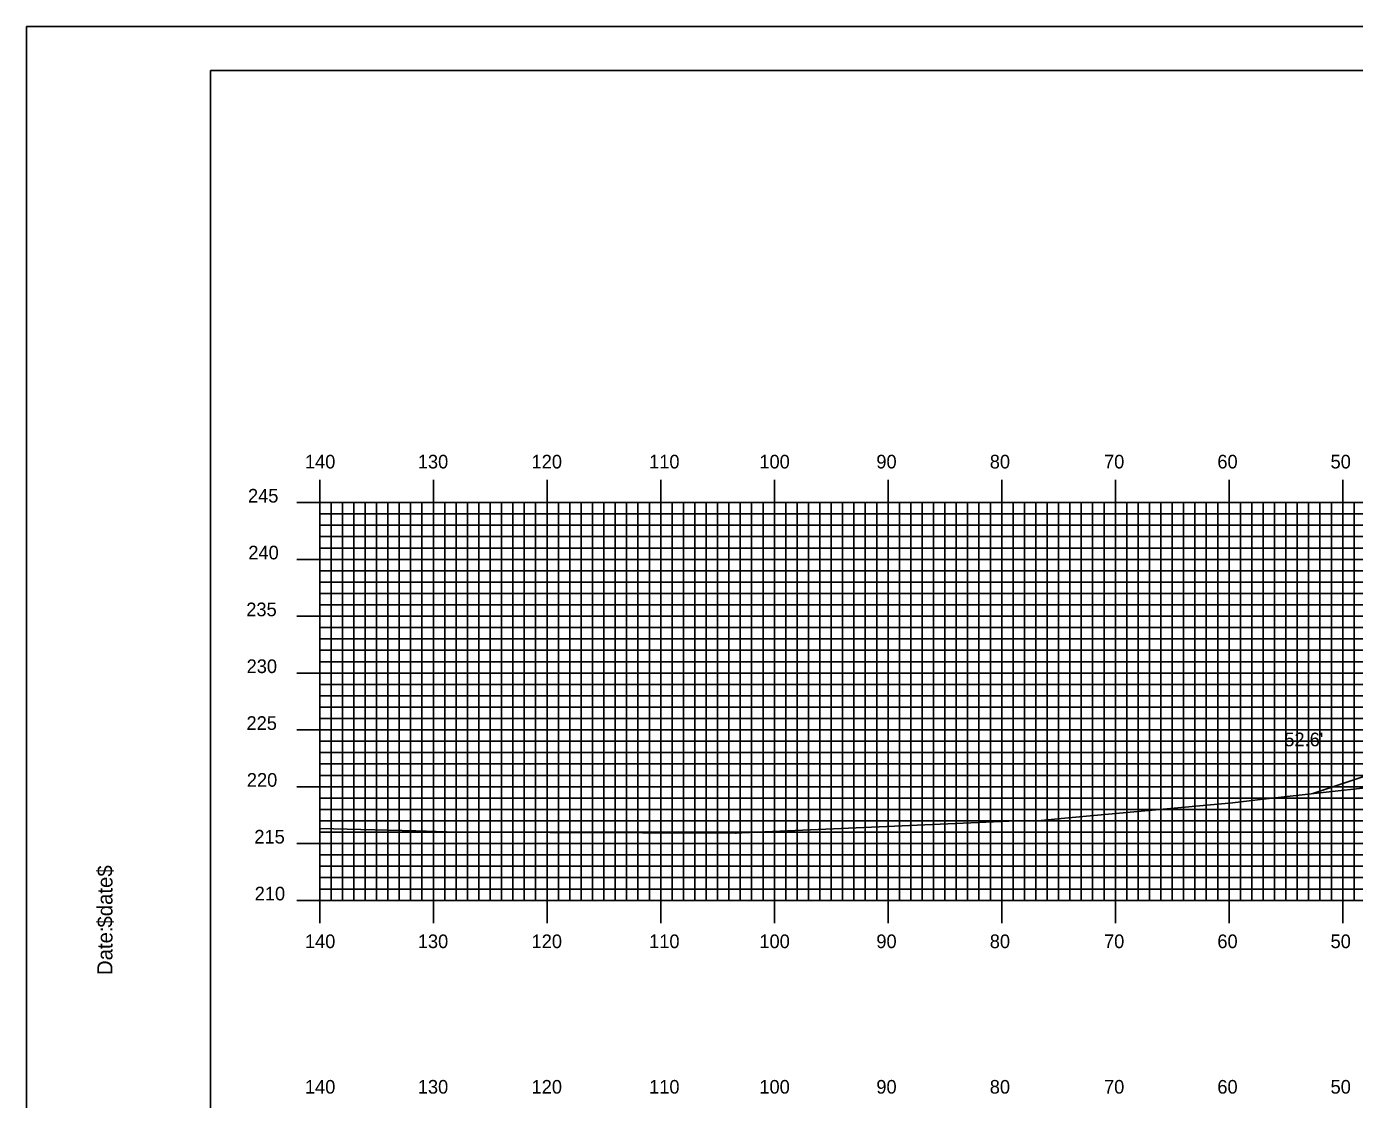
# Model space of a CAD drawing. Extents: x 1818457 to 1818800, y 442591 to 442811.
# Drawn here: x 1818456.9 to 1818573.7, y 442716.2 to 442810.5 of the extents above; entities that cross this region are included whole.
import ezdxf

# ---------------------------------------------------------------- set-up
doc = ezdxf.new("R2010")
doc.units = 0
for name, color, linetype in [('BORDER', 7, 'Continuous'), ('D_Roadway_Centerline', 7, 'Continuous'), ('D_Roadway_SlopeLines', 7, 'Continuous'), ('D_Text_Standard', 7, 'Continuous'), ('H_V ANNOTATION', 7, 'Continuous'), ('MAJOR', 7, 'Continuous'), ('MINOR', 7, 'Continuous'), ('PLOT BOUNDARY', 7, 'Continuous'), ('S_Roadway_Centerline', 7, 'Continuous')]:
    doc.layers.add(name, color=color, linetype=linetype)

msp = doc.modelspace()

# ---------------------------------------------------------------- linework, layer by layer
at = {"layer": 'BORDER'}
msp.add_lwpolyline([(1818473.04, 442596.67), (1818793.04, 442596.67), (1818793.04, 442806.67), (1818473.04, 442806.67)], close=True, dxfattribs=at)
at = {"layer": 'D_Roadway_Centerline'}
msp.add_lwpolyline([(1818570, 442743.06), (1818590.64, 442749.94), (1818592.46, 442750.4), (1818602.64, 442752.94), (1818610.64, 442753.26), (1818622.64, 442753.5), (1818634.64, 442753.26), (1818642.64, 442752.94), (1818652.81, 442750.4), (1818656.81, 442749.4), (1818667.98, 442753.12), (1818669.23, 442753.51), (1818670.48, 442753.82), (1818671.73, 442754.08), (1818672.98, 442754.27)], dxfattribs=at)
at = {"layer": 'D_Roadway_SlopeLines'}
msp.add_lwpolyline([(1818602.64, 442752.94), (1818590.64, 442749.94), (1818570, 442743.06)], dxfattribs=at)
at = {"layer": 'MAJOR'}
for p, q in [((1818482.64, 442770.67), (1818482.64, 442768.67)), ((1818492.64, 442770.67), (1818492.64, 442768.67)), ((1818502.64, 442770.67), (1818502.64, 442768.67)), ((1818512.64, 442770.67), (1818512.64, 442768.67)), ((1818522.64, 442770.67), (1818522.64, 442768.67)), ((1818532.64, 442770.67), (1818532.64, 442768.67)), ((1818542.64, 442770.67), (1818542.64, 442768.67)), ((1818552.64, 442770.67), (1818552.64, 442768.67)), ((1818562.64, 442770.67), (1818562.64, 442768.67)), ((1818572.64, 442770.67), (1818572.64, 442768.67)), ((1818480.63, 442768.67), (1818482.64, 442768.67)), ((1818482.64, 442768.67), (1818762.64, 442768.67)), ((1818482.64, 442733.67), (1818482.64, 442768.67)), ((1818482.64, 442733.67), (1818482.64, 442768.67)), ((1818482.64, 442768.67), (1818762.64, 442768.67)), ((1818492.64, 442733.67), (1818492.64, 442768.67)), ((1818502.64, 442733.67), (1818502.64, 442768.67)), ((1818512.64, 442733.67), (1818512.64, 442768.67)), ((1818522.64, 442733.67), (1818522.64, 442768.67)), ((1818532.64, 442733.67), (1818532.64, 442768.67)), ((1818542.64, 442733.67), (1818542.64, 442768.67)), ((1818552.64, 442733.67), (1818552.64, 442768.67)), ((1818562.64, 442733.67), (1818562.64, 442768.67)), ((1818572.64, 442733.67), (1818572.64, 442768.67)), ((1818480.63, 442763.67), (1818482.64, 442763.67)), ((1818482.64, 442763.67), (1818762.64, 442763.67)), ((1818480.63, 442758.67), (1818482.64, 442758.67)), ((1818482.64, 442758.67), (1818762.64, 442758.67)), ((1818480.63, 442753.67), (1818482.64, 442753.67)), ((1818482.64, 442753.67), (1818762.64, 442753.67)), ((1818480.63, 442748.67), (1818482.64, 442748.67)), ((1818482.64, 442748.67), (1818762.64, 442748.67)), ((1818480.63, 442743.67), (1818482.64, 442743.67)), ((1818482.64, 442743.67), (1818762.64, 442743.67)), ((1818480.63, 442738.67), (1818482.64, 442738.67)), ((1818482.64, 442738.67), (1818762.64, 442738.67)), ((1818480.63, 442733.67), (1818482.64, 442733.67)), ((1818482.64, 442733.67), (1818762.64, 442733.67)), ((1818482.64, 442733.67), (1818762.64, 442733.67)), ((1818482.64, 442731.66), (1818482.64, 442733.67)), ((1818492.64, 442731.66), (1818492.64, 442733.67)), ((1818502.64, 442731.66), (1818502.64, 442733.67)), ((1818512.64, 442731.66), (1818512.64, 442733.67)), ((1818522.64, 442731.66), (1818522.64, 442733.67)), ((1818532.64, 442731.66), (1818532.64, 442733.67)), ((1818542.64, 442731.66), (1818542.64, 442733.67)), ((1818552.64, 442731.66), (1818552.64, 442733.67)), ((1818562.64, 442731.66), (1818562.64, 442733.67)), ((1818572.64, 442731.66), (1818572.64, 442733.67))]:
    msp.add_line(p, q, dxfattribs=at)
at = {"layer": 'MINOR'}
for p, q in [((1818483.64, 442733.67), (1818483.64, 442768.67)), ((1818484.64, 442733.67), (1818484.64, 442768.67)), ((1818485.64, 442733.67), (1818485.64, 442768.67)), ((1818486.64, 442733.67), (1818486.64, 442768.67)), ((1818487.64, 442733.67), (1818487.64, 442768.67)), ((1818488.64, 442733.67), (1818488.64, 442768.67)), ((1818489.64, 442733.67), (1818489.64, 442768.67)), ((1818490.64, 442733.67), (1818490.64, 442768.67)), ((1818491.64, 442733.67), (1818491.64, 442768.67)), ((1818493.64, 442733.67), (1818493.64, 442768.67)), ((1818494.64, 442733.67), (1818494.64, 442768.67)), ((1818495.64, 442733.67), (1818495.64, 442768.67)), ((1818496.64, 442733.67), (1818496.64, 442768.67)), ((1818497.64, 442733.67), (1818497.64, 442768.67)), ((1818498.64, 442733.67), (1818498.64, 442768.67)), ((1818499.64, 442733.67), (1818499.64, 442768.67)), ((1818500.64, 442733.67), (1818500.64, 442768.67)), ((1818501.64, 442733.67), (1818501.64, 442768.67)), ((1818503.64, 442733.67), (1818503.64, 442768.67)), ((1818504.64, 442733.67), (1818504.64, 442768.67)), ((1818505.64, 442733.67), (1818505.64, 442768.67)), ((1818506.64, 442733.67), (1818506.64, 442768.67)), ((1818507.64, 442733.67), (1818507.64, 442768.67)), ((1818508.64, 442733.67), (1818508.64, 442768.67)), ((1818509.64, 442733.67), (1818509.64, 442768.67)), ((1818510.64, 442733.67), (1818510.64, 442768.67)), ((1818511.64, 442733.67), (1818511.64, 442768.67)), ((1818513.64, 442733.67), (1818513.64, 442768.67)), ((1818514.64, 442733.67), (1818514.64, 442768.67)), ((1818515.64, 442733.67), (1818515.64, 442768.67)), ((1818516.64, 442733.67), (1818516.64, 442768.67)), ((1818517.64, 442733.67), (1818517.64, 442768.67)), ((1818518.64, 442733.67), (1818518.64, 442768.67)), ((1818519.64, 442733.67), (1818519.64, 442768.67)), ((1818520.64, 442733.67), (1818520.64, 442768.67)), ((1818521.64, 442733.67), (1818521.64, 442768.67)), ((1818523.64, 442733.67), (1818523.64, 442768.67)), ((1818524.64, 442733.67), (1818524.64, 442768.67)), ((1818525.64, 442733.67), (1818525.64, 442768.67)), ((1818526.64, 442733.67), (1818526.64, 442768.67)), ((1818527.64, 442733.67), (1818527.64, 442768.67)), ((1818528.64, 442733.67), (1818528.64, 442768.67)), ((1818529.64, 442733.67), (1818529.64, 442768.67)), ((1818530.64, 442733.67), (1818530.64, 442768.67)), ((1818531.64, 442733.67), (1818531.64, 442768.67)), ((1818533.64, 442733.67), (1818533.64, 442768.67)), ((1818534.64, 442733.67), (1818534.64, 442768.67)), ((1818535.64, 442733.67), (1818535.64, 442768.67)), ((1818536.64, 442733.67), (1818536.64, 442768.67)), ((1818537.64, 442733.67), (1818537.64, 442768.67)), ((1818538.64, 442733.67), (1818538.64, 442768.67)), ((1818539.64, 442733.67), (1818539.64, 442768.67)), ((1818540.64, 442733.67), (1818540.64, 442768.67)), ((1818541.64, 442733.67), (1818541.64, 442768.67)), ((1818543.64, 442733.67), (1818543.64, 442768.67)), ((1818544.64, 442733.67), (1818544.64, 442768.67)), ((1818545.64, 442733.67), (1818545.64, 442768.67)), ((1818546.64, 442733.67), (1818546.64, 442768.67)), ((1818547.64, 442733.67), (1818547.64, 442768.67)), ((1818548.64, 442733.67), (1818548.64, 442768.67)), ((1818549.64, 442733.67), (1818549.64, 442768.67)), ((1818550.64, 442733.67), (1818550.64, 442768.67)), ((1818551.64, 442733.67), (1818551.64, 442768.67)), ((1818553.64, 442733.67), (1818553.64, 442768.67)), ((1818554.64, 442733.67), (1818554.64, 442768.67)), ((1818555.64, 442733.67), (1818555.64, 442768.67)), ((1818556.64, 442733.67), (1818556.64, 442768.67)), ((1818557.64, 442733.67), (1818557.64, 442768.67)), ((1818558.64, 442733.67), (1818558.64, 442768.67)), ((1818559.64, 442733.67), (1818559.64, 442768.67)), ((1818560.64, 442733.67), (1818560.64, 442768.67)), ((1818561.64, 442733.67), (1818561.64, 442768.67)), ((1818563.64, 442733.67), (1818563.64, 442768.67)), ((1818564.64, 442733.67), (1818564.64, 442768.67)), ((1818565.64, 442733.67), (1818565.64, 442768.67)), ((1818566.64, 442733.67), (1818566.64, 442768.67)), ((1818567.64, 442733.67), (1818567.64, 442768.67)), ((1818568.64, 442733.67), (1818568.64, 442768.67)), ((1818569.64, 442733.67), (1818569.64, 442768.67)), ((1818570.64, 442733.67), (1818570.64, 442768.67)), ((1818571.64, 442733.67), (1818571.64, 442768.67)), ((1818573.64, 442733.67), (1818573.64, 442768.67)), ((1818482.64, 442767.67), (1818762.64, 442767.67)), ((1818482.64, 442767.67), (1818484.64, 442767.67)), ((1818482.64, 442766.67), (1818762.64, 442766.67)), ((1818482.64, 442766.67), (1818484.64, 442766.67)), ((1818482.64, 442765.67), (1818762.64, 442765.67)), ((1818482.64, 442765.67), (1818484.64, 442765.67)), ((1818482.64, 442764.67), (1818762.64, 442764.67)), ((1818482.64, 442764.67), (1818484.64, 442764.67)), ((1818482.64, 442762.67), (1818762.64, 442762.67)), ((1818482.64, 442762.67), (1818484.64, 442762.67)), ((1818482.64, 442761.67), (1818762.64, 442761.67)), ((1818482.64, 442761.67), (1818484.64, 442761.67)), ((1818482.64, 442760.67), (1818762.64, 442760.67)), ((1818482.64, 442760.67), (1818484.64, 442760.67)), ((1818482.64, 442759.67), (1818762.64, 442759.67)), ((1818482.64, 442759.67), (1818484.64, 442759.67)), ((1818482.64, 442757.67), (1818762.64, 442757.67)), ((1818482.64, 442757.67), (1818484.64, 442757.67)), ((1818482.64, 442756.67), (1818762.64, 442756.67)), ((1818482.64, 442756.67), (1818484.64, 442756.67)), ((1818482.64, 442755.67), (1818762.64, 442755.67)), ((1818482.64, 442755.67), (1818484.64, 442755.67)), ((1818482.64, 442754.67), (1818762.64, 442754.67)), ((1818482.64, 442754.67), (1818484.64, 442754.67)), ((1818482.64, 442752.67), (1818762.64, 442752.67)), ((1818482.64, 442752.67), (1818484.64, 442752.67)), ((1818482.64, 442751.67), (1818762.64, 442751.67)), ((1818482.64, 442751.67), (1818484.64, 442751.67)), ((1818482.64, 442750.67), (1818762.64, 442750.67)), ((1818482.64, 442750.67), (1818484.64, 442750.67)), ((1818482.64, 442749.67), (1818762.64, 442749.67)), ((1818482.64, 442749.67), (1818484.64, 442749.67)), ((1818482.64, 442747.67), (1818762.64, 442747.67)), ((1818482.64, 442747.67), (1818484.64, 442747.67)), ((1818482.64, 442746.67), (1818762.64, 442746.67)), ((1818482.64, 442746.67), (1818484.64, 442746.67)), ((1818482.64, 442745.67), (1818762.64, 442745.67)), ((1818482.64, 442745.67), (1818484.64, 442745.67)), ((1818482.64, 442744.67), (1818762.64, 442744.67)), ((1818482.64, 442744.67), (1818484.64, 442744.67)), ((1818482.64, 442742.67), (1818762.64, 442742.67)), ((1818482.64, 442742.67), (1818484.64, 442742.67)), ((1818482.64, 442741.67), (1818762.64, 442741.67)), ((1818482.64, 442741.67), (1818484.64, 442741.67)), ((1818482.64, 442740.67), (1818762.64, 442740.67)), ((1818482.64, 442740.67), (1818484.64, 442740.67)), ((1818482.64, 442739.67), (1818762.64, 442739.67)), ((1818482.64, 442739.67), (1818484.64, 442739.67)), ((1818482.64, 442737.67), (1818762.64, 442737.67)), ((1818482.64, 442737.67), (1818484.64, 442737.67)), ((1818482.64, 442736.67), (1818762.64, 442736.67)), ((1818482.64, 442736.67), (1818484.64, 442736.67)), ((1818482.64, 442735.67), (1818762.64, 442735.67)), ((1818482.64, 442735.67), (1818484.64, 442735.67)), ((1818482.64, 442734.67), (1818762.64, 442734.67)), ((1818482.64, 442734.67), (1818484.64, 442734.67))]:
    msp.add_line(p, q, dxfattribs=at)
at = {"layer": 'PLOT BOUNDARY'}
msp.add_lwpolyline([(1818456.85, 442590.55), (1818796.85, 442590.55), (1818796.85, 442810.55), (1818456.85, 442810.55)], close=True, dxfattribs=at)
at = {"layer": 'S_Roadway_Centerline'}
msp.add_lwpolyline([(1818482.64, 442740), (1818491.09, 442739.78), (1818494.7, 442739.66), (1818519.22, 442739.59), (1818519.26, 442739.59), (1818519.28, 442739.59), (1818519.79, 442739.61), (1818543.27, 442740.63), (1818546.1, 442740.71), (1818547.87, 442740.88), (1818555.55, 442741.57), (1818562.93, 442742.24), (1818565.65, 442742.58), (1818580.46, 442744.22)], dxfattribs=at)

# ---------------------------------------------------------------- texts
at = {"layer": 'BORDER'}
for s, p in [('$date$', (1818464.41, 442731.28)), ('Date:', (1818464.41, 442727.1))]:
    msp.add_text(s, height=1.339, rotation=90, dxfattribs=at).set_placement(p)
at = {"layer": 'D_Text_Standard'}
msp.add_text("52.6'", height=1.2, dxfattribs=at).set_placement((1818567.5, 442747.23))
at = {"layer": 'H_V ANNOTATION'}
for s, p in [('140', (1818481.34, 442771.67)), ('130', (1818491.27, 442771.67)), ('120', (1818501.28, 442771.67)), ('110', (1818511.62, 442771.67)), ('100', (1818521.32, 442771.67)), ('90', (1818531.61, 442771.67)), ('80', (1818541.59, 442771.67)), ('70', (1818551.64, 442771.67)), ('60', (1818561.61, 442771.67)), ('50', (1818571.57, 442771.67)), ('245', (1818476.33, 442768.67)), ('240', (1818476.36, 442763.67)), ('235', (1818476.18, 442758.67)), ('230', (1818476.21, 442753.67)), ('225', (1818476.2, 442748.67)), ('220', (1818476.23, 442743.67)), ('215', (1818476.89, 442738.67)), ('210', (1818476.92, 442733.67)), ('140', (1818481.34, 442729.47)), ('130', (1818491.27, 442729.47)), ('120', (1818501.28, 442729.47)), ('110', (1818511.62, 442729.47)), ('100', (1818521.32, 442729.47)), ('90', (1818531.61, 442729.47)), ('80', (1818541.59, 442729.47)), ('70', (1818551.64, 442729.47)), ('60', (1818561.61, 442729.47)), ('50', (1818571.57, 442729.47)), ('140', (1818481.34, 442716.67)), ('130', (1818491.27, 442716.67)), ('120', (1818501.28, 442716.67)), ('110', (1818511.62, 442716.67)), ('100', (1818521.32, 442716.67)), ('90', (1818531.61, 442716.67)), ('80', (1818541.59, 442716.67)), ('70', (1818551.64, 442716.67)), ('60', (1818561.61, 442716.67)), ('50', (1818571.57, 442716.67))]:
    msp.add_text(s, height=1.2, dxfattribs=at).set_placement(p)
at = {"layer": 'MAJOR'}
msp.add_text('-', height=0.012, dxfattribs=at).set_placement((1818482.63, 442733.67))

doc.saveas('drawing.dxf')
